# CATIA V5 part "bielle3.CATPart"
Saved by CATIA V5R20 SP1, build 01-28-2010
Part number: Part1.1.2.3
Bounding box of the stored display mesh (mm): x 33 to 87, y 0 to 5, z 28.093 to 41.907
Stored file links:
  E:\EDELI\gcausse\Edeli_2012_685_gcausse\bielle3.CATPart
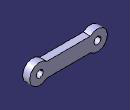
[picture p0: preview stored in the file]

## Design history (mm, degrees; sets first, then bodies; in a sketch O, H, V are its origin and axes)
Parameters
  long = 0.04
  diamtrou = 0.005
Body1 (main body)
  Sketch1 on zx-plane, origin (0, 0, 0), H (-1, 0, 0), V (0, 0, 1)
    line L1 (-44.899, 40) -> (-75.101, 40)
    line L2 (-44.899, 30) -> (-75.101, 30)
    arc A1 centre (-40, 35) radius 7 from (-44.899, 40) to (-44.899, 30) cw
    point P5 (-40, 35)
    point P6 (-35.101, 30)
    arc A2 centre (-80, 35) radius 7 from (-75.101, 40) to (-75.101, 30) ccw
    point P7 (-80, 35)
    circle A3 centre (-40, 35) radius 2.5
    distance P7 L1 = 5
    distance P5 L2 = 5
    distance L2 L1 = 10
    radius A1 = 7
    radius A2 = 7
    distance P5 P7 = 40 {= long}
    radius A3 = 2.5
    horizontal: L1 H, L2 H
    coincidence: A1 P6, P6 L2
  Pad1: profile Sketch1, direction (0, 1, 0), length 5
  Sketch2 on end face of Pad1, origin (0, 5, 0), H (-1, 0, 0), V (0, 0, 1)
    circle A1 centre (-80, 35) radius 2.5
    reference projected arc E1 centre (-80, 35) radius 7 from (-75.101, 40) to (-75.101, 30) ccw from edge [face of Pad1 from Sketch1.A2 | end face of Pad1]
    reference projected arc E2 centre (-80, 35) radius 7 from (-75.101, 40) to (-75.101, 30) ccw from edge [face of Pad1 from Sketch1.A2 | end face of Pad1]
    radius A1 = 2.5
    radius E2 = 7 (reference)
    concentricity: A1 E1
  Pad2: profile Sketch2, direction (0, 1, 0), length 0, opposite side length 5
  Sketch3 on face of Pad2, origin (0, 5, 0), H (-1, 0, 0), V (0, 0, 1)
    circle A1 centre (-80, 35) radius 2.5
    reference projected arc E1 centre (-80, 35) radius 7 from (-75.101, 40) to (-75.101, 30) ccw from edge [face of Pad1 from Sketch1.A2 | end face of Pad1]
    reference projected arc E2 centre (-80, 35) radius 7 from (-75.101, 40) to (-75.101, 30) ccw from edge [face of Pad1 from Sketch1.A2 | end face of Pad1]
    radius A1 = 2.5
    radius E2 = 7 (reference)
    concentricity: A1 E1
  Pocket1: profile Sketch3, direction (0, -1, 0), length 5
